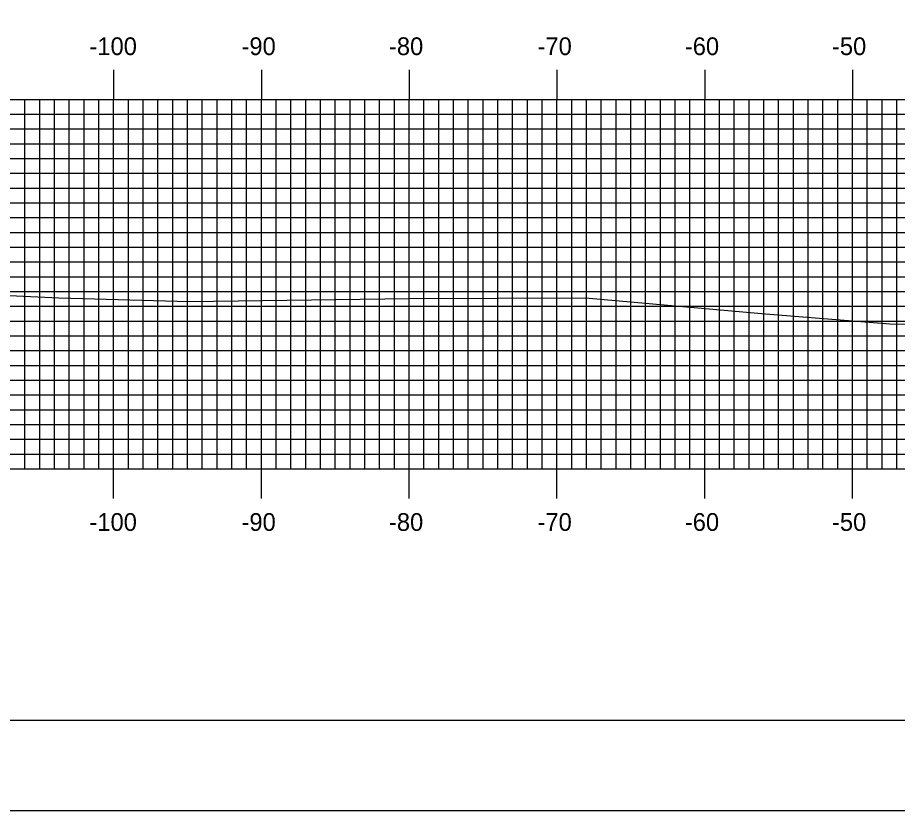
# Model space of a CAD drawing. Extents: x 852087 to 852430, y 366898 to 367118.
# Drawn here: x 852146 to 852205.6, y 366898.4 to 366952 of the extents above; entities that cross this region are included whole.
import ezdxf

# ---------------------------------------------------------------- set-up
doc = ezdxf.new("R2010")
doc.units = 0
for name, color, linetype in [('BORDER', 7, 'Continuous'), ('H_V ANNOTATION', 7, 'Continuous'), ('MAJOR', 7, 'Continuous'), ('MINOR', 7, 'Continuous'), ('PLOT BOUNDARY', 7, 'Continuous'), ('S_Roadway_Centerline', 7, 'Continuous')]:
    doc.layers.add(name, color=color, linetype=linetype)

msp = doc.modelspace()

# ---------------------------------------------------------------- linework, layer by layer
at = {"layer": 'BORDER'}
msp.add_lwpolyline([(852102.931, 366904.473), (852422.931, 366904.473), (852422.931, 367114.473), (852102.931, 367114.473)], close=True, dxfattribs=at)
at = {"layer": 'MAJOR'}
for p, q in [((852152.531, 366948.477), (852152.531, 366946.473)), ((852162.531, 366948.477), (852162.531, 366946.473)), ((852172.531, 366948.477), (852172.531, 366946.473)), ((852182.531, 366948.477), (852182.531, 366946.473)), ((852192.531, 366948.477), (852192.531, 366946.473)), ((852202.531, 366948.477), (852202.531, 366946.473)), ((852112.531, 366946.473), (852392.531, 366946.473)), ((852112.531, 366946.473), (852392.531, 366946.473)), ((852152.531, 366921.473), (852152.531, 366946.473)), ((852162.531, 366921.473), (852162.531, 366946.473)), ((852172.531, 366921.473), (852172.531, 366946.473)), ((852182.531, 366921.473), (852182.531, 366946.473)), ((852192.531, 366921.473), (852192.531, 366946.473)), ((852202.531, 366921.473), (852202.531, 366946.473)), ((852112.531, 366941.473), (852392.531, 366941.473)), ((852112.531, 366936.473), (852392.531, 366936.473)), ((852112.531, 366931.473), (852392.531, 366931.473)), ((852112.531, 366926.473), (852392.531, 366926.473)), ((852112.531, 366921.473), (852392.531, 366921.473)), ((852112.531, 366921.473), (852392.531, 366921.473)), ((852152.531, 366919.469), (852152.531, 366921.473)), ((852162.531, 366919.469), (852162.531, 366921.473)), ((852172.531, 366919.469), (852172.531, 366921.473)), ((852182.531, 366919.469), (852182.531, 366921.473)), ((852192.531, 366919.469), (852192.531, 366921.473)), ((852202.531, 366919.469), (852202.531, 366921.473))]:
    msp.add_line(p, q, dxfattribs=at)
at = {"layer": 'MINOR'}
for p, q in [((852146.531, 366921.473), (852146.531, 366946.473)), ((852147.531, 366921.473), (852147.531, 366946.473)), ((852148.531, 366921.473), (852148.531, 366946.473)), ((852149.531, 366921.473), (852149.531, 366946.473)), ((852150.531, 366921.473), (852150.531, 366946.473)), ((852151.531, 366921.473), (852151.531, 366946.473)), ((852153.531, 366921.473), (852153.531, 366946.473)), ((852154.531, 366921.473), (852154.531, 366946.473)), ((852155.531, 366921.473), (852155.531, 366946.473)), ((852156.531, 366921.473), (852156.531, 366946.473)), ((852157.531, 366921.473), (852157.531, 366946.473)), ((852158.531, 366921.473), (852158.531, 366946.473)), ((852159.531, 366921.473), (852159.531, 366946.473)), ((852160.531, 366921.473), (852160.531, 366946.473)), ((852161.531, 366921.473), (852161.531, 366946.473)), ((852163.531, 366921.473), (852163.531, 366946.473)), ((852164.531, 366921.473), (852164.531, 366946.473)), ((852165.531, 366921.473), (852165.531, 366946.473)), ((852166.531, 366921.473), (852166.531, 366946.473)), ((852167.531, 366921.473), (852167.531, 366946.473)), ((852168.531, 366921.473), (852168.531, 366946.473)), ((852169.531, 366921.473), (852169.531, 366946.473)), ((852170.531, 366921.473), (852170.531, 366946.473)), ((852171.531, 366921.473), (852171.531, 366946.473)), ((852173.531, 366921.473), (852173.531, 366946.473)), ((852174.531, 366921.473), (852174.531, 366946.473)), ((852175.531, 366921.473), (852175.531, 366946.473)), ((852176.531, 366921.473), (852176.531, 366946.473)), ((852177.531, 366921.473), (852177.531, 366946.473)), ((852178.531, 366921.473), (852178.531, 366946.473)), ((852179.531, 366921.473), (852179.531, 366946.473)), ((852180.531, 366921.473), (852180.531, 366946.473)), ((852181.531, 366921.473), (852181.531, 366946.473)), ((852183.531, 366921.473), (852183.531, 366946.473)), ((852184.531, 366921.473), (852184.531, 366946.473)), ((852185.531, 366921.473), (852185.531, 366946.473)), ((852186.531, 366921.473), (852186.531, 366946.473)), ((852187.531, 366921.473), (852187.531, 366946.473)), ((852188.531, 366921.473), (852188.531, 366946.473)), ((852189.531, 366921.473), (852189.531, 366946.473)), ((852190.531, 366921.473), (852190.531, 366946.473)), ((852191.531, 366921.473), (852191.531, 366946.473)), ((852193.531, 366921.473), (852193.531, 366946.473)), ((852194.531, 366921.473), (852194.531, 366946.473)), ((852195.531, 366921.473), (852195.531, 366946.473)), ((852196.531, 366921.473), (852196.531, 366946.473)), ((852197.531, 366921.473), (852197.531, 366946.473)), ((852198.531, 366921.473), (852198.531, 366946.473)), ((852199.531, 366921.473), (852199.531, 366946.473)), ((852200.531, 366921.473), (852200.531, 366946.473)), ((852201.531, 366921.473), (852201.531, 366946.473)), ((852203.531, 366921.473), (852203.531, 366946.473)), ((852204.531, 366921.473), (852204.531, 366946.473)), ((852205.531, 366921.473), (852205.531, 366946.473)), ((852112.531, 366945.473), (852392.531, 366945.473)), ((852112.531, 366944.473), (852392.531, 366944.473)), ((852112.531, 366943.473), (852392.531, 366943.473)), ((852112.531, 366942.473), (852392.531, 366942.473)), ((852112.531, 366940.473), (852392.531, 366940.473)), ((852112.531, 366939.473), (852392.531, 366939.473)), ((852112.531, 366938.473), (852392.531, 366938.473)), ((852112.531, 366937.473), (852392.531, 366937.473)), ((852112.531, 366935.473), (852392.531, 366935.473)), ((852112.531, 366934.473), (852392.531, 366934.473)), ((852112.531, 366933.473), (852392.531, 366933.473)), ((852112.531, 366932.473), (852392.531, 366932.473)), ((852112.531, 366930.473), (852392.531, 366930.473)), ((852112.531, 366929.473), (852392.531, 366929.473)), ((852112.531, 366928.473), (852392.531, 366928.473)), ((852112.531, 366927.473), (852392.531, 366927.473)), ((852112.531, 366925.473), (852392.531, 366925.473)), ((852112.531, 366924.473), (852392.531, 366924.473)), ((852112.531, 366923.473), (852392.531, 366923.473)), ((852112.531, 366922.473), (852392.531, 366922.473))]:
    msp.add_line(p, q, dxfattribs=at)
at = {"layer": 'PLOT BOUNDARY'}
msp.add_lwpolyline([(852086.744, 366898.355), (852426.744, 366898.355), (852426.744, 367118.355), (852086.744, 367118.355)], close=True, dxfattribs=at)
at = {"layer": 'S_Roadway_Centerline'}
msp.add_lwpolyline([(852112.531, 366935.362), (852132.584, 366933.803), (852148.824, 366933.037), (852157.644, 366932.807), (852172.522, 366933.007), (852184.459, 366933.056), (852196.363, 366931.976), (852205.055, 366931.276), (852209.269, 366931.23)], dxfattribs=at)

# ---------------------------------------------------------------- texts
at = {"layer": 'H_V ANNOTATION'}
for s, p in [('-100', (852150.893, 366949.473)), ('-90', (852161.182, 366949.473)), ('-80', (852171.161, 366949.473)), ('-70', (852181.214, 366949.473)), ('-60', (852191.182, 366949.473)), ('-50', (852201.139, 366949.473)), ('-100', (852150.893, 366917.273)), ('-90', (852161.182, 366917.273)), ('-80', (852171.161, 366917.273)), ('-70', (852181.214, 366917.273)), ('-60', (852191.182, 366917.273)), ('-50', (852201.139, 366917.273))]:
    msp.add_text(s, height=1.2, dxfattribs=at).set_placement(p)

doc.saveas('drawing.dxf')
